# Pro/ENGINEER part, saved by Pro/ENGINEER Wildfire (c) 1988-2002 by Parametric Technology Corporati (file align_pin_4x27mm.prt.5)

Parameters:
  PTNUM = "A_1B_3-Y48048"
  PTNAME = "20_DEG_PRESSURE_ANGLE_BEVEL_GEARS-48,32_&_24_PITCH"
  MFG = "Stock_Drive_Products"
  WEIGHT = "*"
  MATERIAL = "BRASS"
  DIAMETRICAL_PITCH = "48"
  TEETH = "48"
